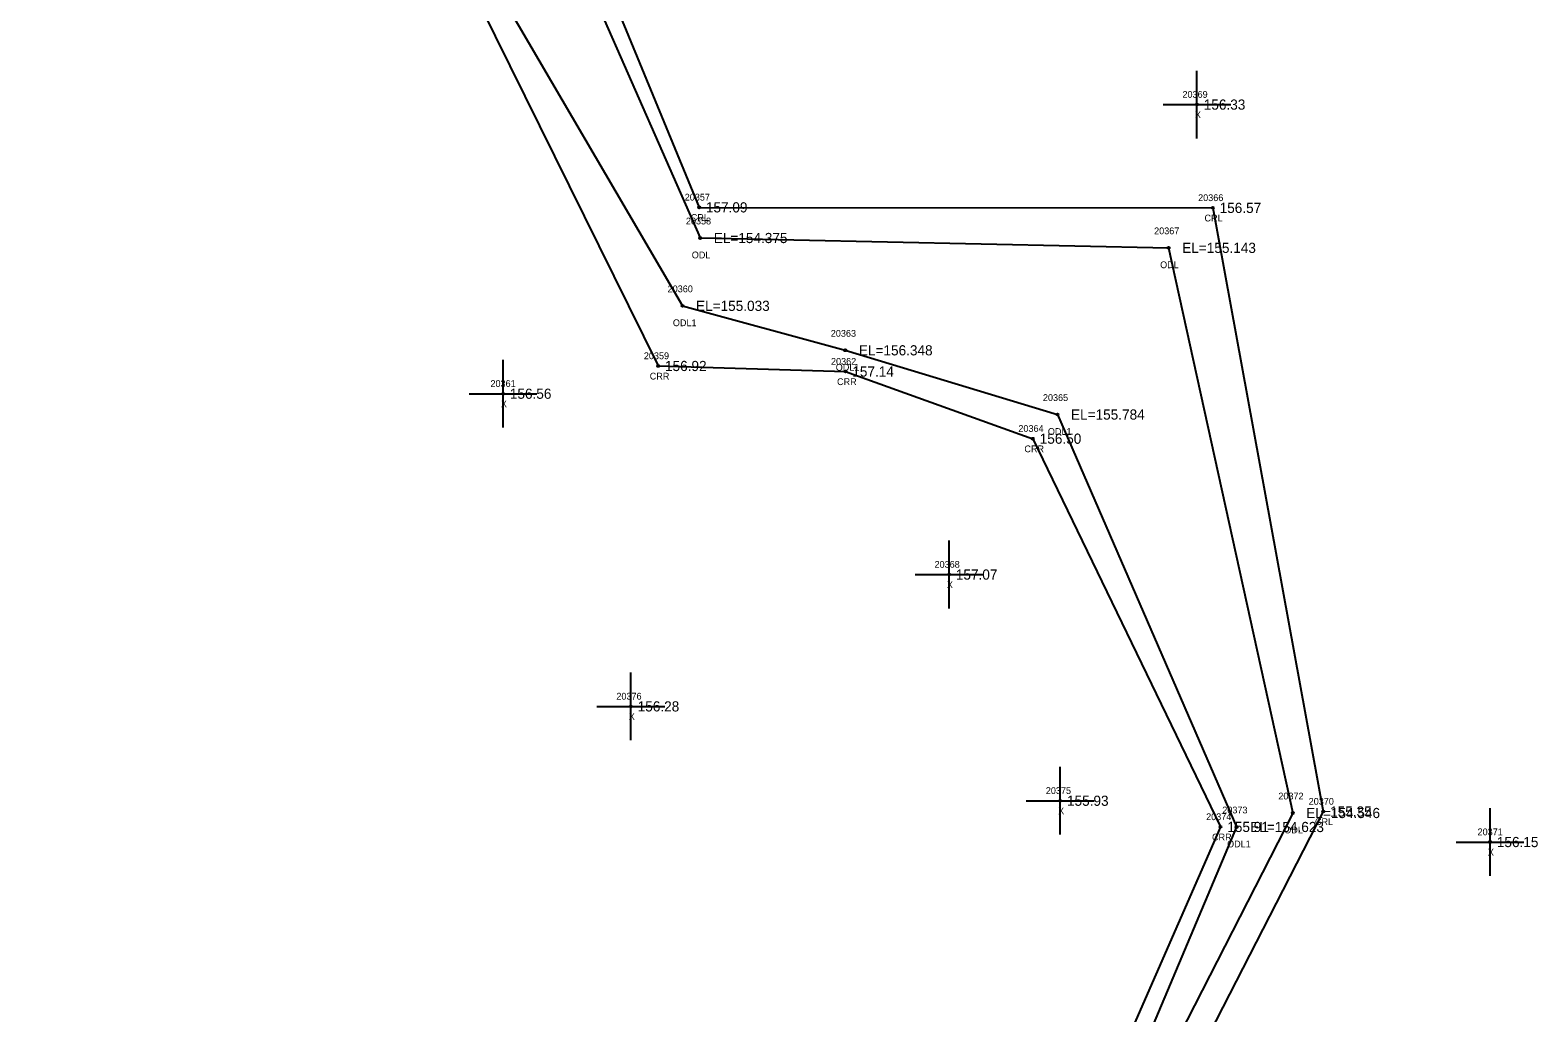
# Model space of a CAD drawing. Extents: x 2381545 to 2382928, y 1029933 to 1030589.
# Drawn here: x 2382160.7 to 2382383.1, y 1030095.3 to 1030240.2 of the extents above; entities that cross this region are included whole.
import ezdxf

# ---------------------------------------------------------------- set-up
doc = ezdxf.new("R2010")
doc.units = 0
for name, color, linetype in [('RD_EX_H2O', 7, 'Continuous'), ('RD_EX_H2O_txCode', 7, 'Continuous'), ('RD_EX_Misc', 7, 'Continuous'), ('RD_EX_Misc_txCode', 7, 'Continuous'), ('RD_EX_TX_H2O_ELEV', 7, 'Continuous'), ('RD_EX_TX_Misc_ELEV', 7, 'Continuous'), ('RD_SMD_Locator', 7, 'Continuous')]:
    doc.layers.add(name, color=color, linetype=linetype)

msp = doc.modelspace()

# ---------------------------------------------------------------- linework, layer by layer
at = {"layer": 'RD_EX_H2O'}
for points in [[(2382228.76, 1030407.08), (2382229.33, 1030393.42), (2382229.44, 1030376.02), (2382235.1, 1030355.5), (2382240.51, 1030349.49), (2382245.56, 1030316.86), (2382248.97, 1030289.05), (2382238.04, 1030280.56), (2382242.49, 1030255.05), (2382259.38, 1030214.05), (2382335.14, 1030213.97), (2382351.43, 1030124.97), (2382330.65, 1030084.53), (2382333.22, 1030050.31), (2382344.99, 1030019.27), (2382333.68, 1029961.92)], [(2382160.73, 1030399.39), (2382197.66, 1030393.98), (2382201.16, 1030391.22), (2382207.75, 1030374.4), (2382216.83, 1030343.34), (2382214.66, 1030277.58), (2382224.95, 1030248.16), (2382253.35, 1030190.66), (2382280.97, 1030189.84), (2382308.61, 1030179.94), (2382336.27, 1030122.7), (2382320.51, 1030086.69), (2382321.43, 1030050.4), (2382332.53, 1030017.35), (2382333.68, 1029961.92)], [(2382220.88, 1030388.74), (2382227.06, 1030360.93), (2382229.81, 1030345.11), (2382235.02, 1030321.93), (2382245.69, 1030289.44), (2382231.02, 1030286.27), (2382239.27, 1030255.62), (2382259.54, 1030209.53), (2382328.62, 1030208.08), (2382346.92, 1030124.75), (2382326.86, 1030085.52), (2382331.57, 1030050.13), (2382343.53, 1030018.97), (2382333.68, 1029961.92)], [(2382213.26, 1030387.6), (2382221.81, 1030359.48), (2382223.97, 1030346.38), (2382221.92, 1030320.69), (2382220.3, 1030284.96), (2382227.77, 1030249.4), (2382256.92, 1030199.53), (2382280.94, 1030192.97), (2382312.22, 1030183.5), (2382338.65, 1030122.69), (2382323.29, 1030086.32), (2382328.28, 1030050.33), (2382335.32, 1030017.57), (2382333.68, 1029961.92)]]:
    msp.add_lwpolyline(points, dxfattribs=at)
at = {"layer": 'RD_EX_Misc'}
for p, q in [((2382332.8, 1030224.2), (2382332.8, 1030234.2)), ((2382327.8, 1030229.2), (2382337.8, 1030229.2)), ((2382230.47, 1030181.57), (2382230.47, 1030191.57)), ((2382225.47, 1030186.57), (2382235.47, 1030186.57)), ((2382296.24, 1030154.91), (2382296.24, 1030164.91)), ((2382291.24, 1030159.91), (2382301.24, 1030159.91)), ((2382249.32, 1030135.47), (2382249.32, 1030145.47)), ((2382244.32, 1030140.47), (2382254.32, 1030140.47)), ((2382312.63, 1030121.56), (2382312.63, 1030131.56)), ((2382307.63, 1030126.56), (2382317.63, 1030126.56)), ((2382376.02, 1030115.47), (2382376.02, 1030125.47)), ((2382371.02, 1030120.47), (2382381.02, 1030120.47))]:
    msp.add_line(p, q, dxfattribs=at)
at = {"layer": 'RD_SMD_Locator'}
for centre in [(2382332.8, 1030229.2), (2382259.38, 1030214.05), (2382335.14, 1030213.97), (2382259.54, 1030209.53), (2382328.62, 1030208.08), (2382256.92, 1030199.53), (2382280.94, 1030192.97), (2382253.35, 1030190.66), (2382280.97, 1030189.84), (2382230.47, 1030186.57), (2382312.22, 1030183.5), (2382308.61, 1030179.94), (2382296.24, 1030159.91), (2382249.32, 1030140.47), (2382312.63, 1030126.56), (2382346.92, 1030124.75), (2382351.43, 1030124.97), (2382336.27, 1030122.7), (2382338.65, 1030122.69), (2382376.02, 1030120.47)]:
    msp.add_circle(centre, 0.15, dxfattribs=at)

# ---------------------------------------------------------------- texts
at = {"layer": 'RD_EX_H2O_txCode'}
for s, p in [('20357', (2382257.26, 1030215.05)), ('20366', (2382332.97, 1030214.97)), ('CRL', (2382258.15, 1030212.05)), ('CRL', (2382333.91, 1030211.97)), ('20358', (2382257.43, 1030211.53)), ('20367', (2382326.48, 1030210.08)), ('ODL', (2382258.3, 1030206.53)), ('ODL', (2382327.37, 1030205.08)), ('20360', (2382254.74, 1030201.53)), ('ODL1', (2382255.51, 1030196.53)), ('20363', (2382278.8, 1030194.97)), ('20359', (2382251.23, 1030191.66)), ('20362', (2382278.83, 1030190.84)), ('ODL1', (2382279.53, 1030189.97)), ('CRR', (2382252.1, 1030188.66)), ('CRR', (2382279.72, 1030187.84)), ('20365', (2382310.08, 1030185.5)), ('20364', (2382306.46, 1030180.94)), ('ODL1', (2382310.81, 1030180.5)), ('CRR', (2382307.35, 1030177.94)), ('20372', (2382344.8, 1030126.75)), ('20370', (2382349.27, 1030125.97)), ('20374', (2382334.15, 1030123.7)), ('20373', (2382336.53, 1030124.69)), ('CRL', (2382350.2, 1030122.97)), ('CRR', (2382335.02, 1030120.7)), ('ODL', (2382345.67, 1030121.75)), ('ODL1', (2382337.24, 1030119.69))]:
    msp.add_text(s, height=1, dxfattribs=at).set_placement(p)
at = {"layer": 'RD_EX_Misc_txCode'}
for s, p in [('20369', (2382330.66, 1030230.2)), ('X', (2382332.49, 1030227.2)), ('20361', (2382228.61, 1030187.57)), ('X', (2382230.15, 1030184.57)), ('20368', (2382294.1, 1030160.91)), ('X', (2382295.92, 1030157.91)), ('20376', (2382247.18, 1030141.47)), ('X', (2382249.01, 1030138.47)), ('20375', (2382310.51, 1030127.56)), ('X', (2382312.32, 1030124.56)), ('20371', (2382374.18, 1030121.47)), ('X', (2382375.7, 1030118.47))]:
    msp.add_text(s, height=1, dxfattribs=at).set_placement(p)
at = {"layer": 'RD_EX_TX_H2O_ELEV'}
for s, p in [('157.09', (2382260.38, 1030213.3)), ('156.57', (2382336.14, 1030213.22)), ('EL=154.375', (2382261.54, 1030208.78)), ('EL=155.143', (2382330.62, 1030207.33)), ('EL=155.033', (2382258.92, 1030198.78)), ('EL=156.348', (2382282.94, 1030192.22)), ('156.92', (2382254.35, 1030189.91)), ('157.14', (2382281.97, 1030189.09)), ('EL=155.784', (2382314.22, 1030182.75)), ('156.50', (2382309.61, 1030179.19)), ('EL=154.546', (2382348.92, 1030124)), ('155.35', (2382352.43, 1030124.22)), ('155.91', (2382337.27, 1030121.95)), ('EL=154.623', (2382340.65, 1030121.94))]:
    msp.add_text(s, height=1.5, dxfattribs=at).set_placement(p)
at = {"layer": 'RD_EX_TX_Misc_ELEV'}
for s, p in [('156.33', (2382333.8, 1030228.45)), ('156.56', (2382231.47, 1030185.82)), ('157.07', (2382297.24, 1030159.16)), ('156.28', (2382250.32, 1030139.72)), ('155.93', (2382313.63, 1030125.81)), ('156.15', (2382377.02, 1030119.72))]:
    msp.add_text(s, height=1.5, dxfattribs=at).set_placement(p)

doc.saveas('drawing.dxf')
